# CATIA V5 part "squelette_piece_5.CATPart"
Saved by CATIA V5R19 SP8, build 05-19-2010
Part number: squelette_piece_5
Publications: "Point.6", "Point.5", "Droite.3", "Point.4", "Point.3", "Droite.2", "Point.2", "Point.1", "Droite.1"
Bounding box of the stored display mesh (mm): x -25 to 50, y 0 to 134.7, z -634.7 to -500
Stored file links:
  G:\EU_thinkMotion\CFAO_2010\SIL_groupe1\SIL_groupe1\A reprendre\lalpha\lalpha\Alpha.mécanisme\squelette_piece_5.CATPart
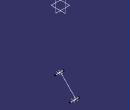
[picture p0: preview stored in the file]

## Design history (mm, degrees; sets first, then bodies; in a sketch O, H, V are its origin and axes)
Set1
  Line1: type PtPt, FirstPoint Point1, SecondPoint Point2
  Point1: stored without definition
  Point2: stored without definition
  Line2: type PtPt, FirstPoint Point3, SecondPoint Point4, Start 25, End 25
  Point3: stored without definition
  Point4: stored without definition
  Line3: type PtPt, FirstPoint Point5, SecondPoint Point6, Start 25, End 25
  Point5: stored without definition
  Point6: stored without definition
Body1 (main body)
